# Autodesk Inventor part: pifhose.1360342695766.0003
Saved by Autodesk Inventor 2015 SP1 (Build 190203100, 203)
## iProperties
IsCustomPart: 1
Company: Parker Hannifin
Created: 2013-02
Material: Rubber
Description: Tömlő
Document SubType Name: Modeling
Standard: Parker
Designer: Marci
Manufacturer: Parker
Language: hu-HU
Size Designation: 1/4 - 5
Categories: <MemberInstance><Categories><Category DisplayName="Csővezetékek" InternalName="4347fa0f-2144-441d-94cd-e3e15c92b736" Mnemonic="TUBEANDPIPE"><CategoryParameter D
Stock Number: Parker hidraulikatömlő - No Skive 1/4
Density: 1 g/cm^3
Appearance: Rubber - Black - Version 1.1
NAME: PIPING: Parker Hydraulic Hose - No Skive
DATA: <meta><inlinegroups number="1" deflen="12.7"></inlinegroups><connections number="2"></connections><angles><a>3.14159265358979</a></angles></meta>
L: 7,377 in
PL: 7,377 in
RPL: 7,500 in
OPL: 7,377 in
ROPL: 7,500 in
Author: Marci
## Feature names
1. Sweep1
## Parameters: ID = 6.35 mm, OD = 14.986 mm, L = 187.3758 mm, PL = 187.3758 mm, Size_Designation = 2.5 mm, d6 = 0, RPL = 190.5 mm, OPL = 187.3758 mm, ROPL = 190.5 mm, d7 = 0
